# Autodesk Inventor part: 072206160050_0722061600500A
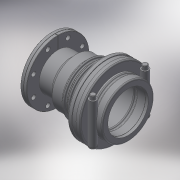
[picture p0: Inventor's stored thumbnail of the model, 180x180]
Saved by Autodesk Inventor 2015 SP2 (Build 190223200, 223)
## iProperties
Created: 2017-05
Part Number: 072206160050_0722061600500A
Material: Generic
Description: PLASSON COMPRESSION FLANGE ADAPTOR 160-5"
Document SubType Name: Modeling
Designer: KIM
Density: 1 g/cm^3
Appearance: Default
Author: KIM
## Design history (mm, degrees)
derived "072206.ipt"
feature "Solid1::072206.ipt"
tag "TaggingFeature1"
body "Solid1"
other parameters: "d0" = 304, "d3" = 208, "d4" = 192, "d5" = 4.8, "d6" = 51, "d7" = 274.4, "d9" = 204, "d10" = 51, "d11" = 9.6, "d12" = 51, "d13" = 10.2, "d15" = 4.8, "d17" = 161.6, "d18" = 11.55, "d19" = 0, "d21" = 0, "d23" = 20.16, "d24" = 16, "d25" = 0, "d26" = 1.6, "d29" = 0.1, "d30" = 8, "d31" = 0, "d32" = 4.8, "d33" = 125, "d41" = 135 deg, "d42" = 24.32, "d43" = 1, "d44" = 1, "d46" = 76, "d47" = 18, "d48" = 105, "d50" = 0, "d52" = 360 deg, "d60" = 22.5 deg, "d61" = 2, "d62" = 1, "d63" = 12.16, "d64" = 0, "d66" = 360 deg, "d68" = 1.25, "d71" = 1, "d72" = 1, "d75" = 360 deg, "l_" = 204, "H_" = 304, "S_" = 18, "Dn_" = 125, "d16" = 46.2, "d22" = 28.8
